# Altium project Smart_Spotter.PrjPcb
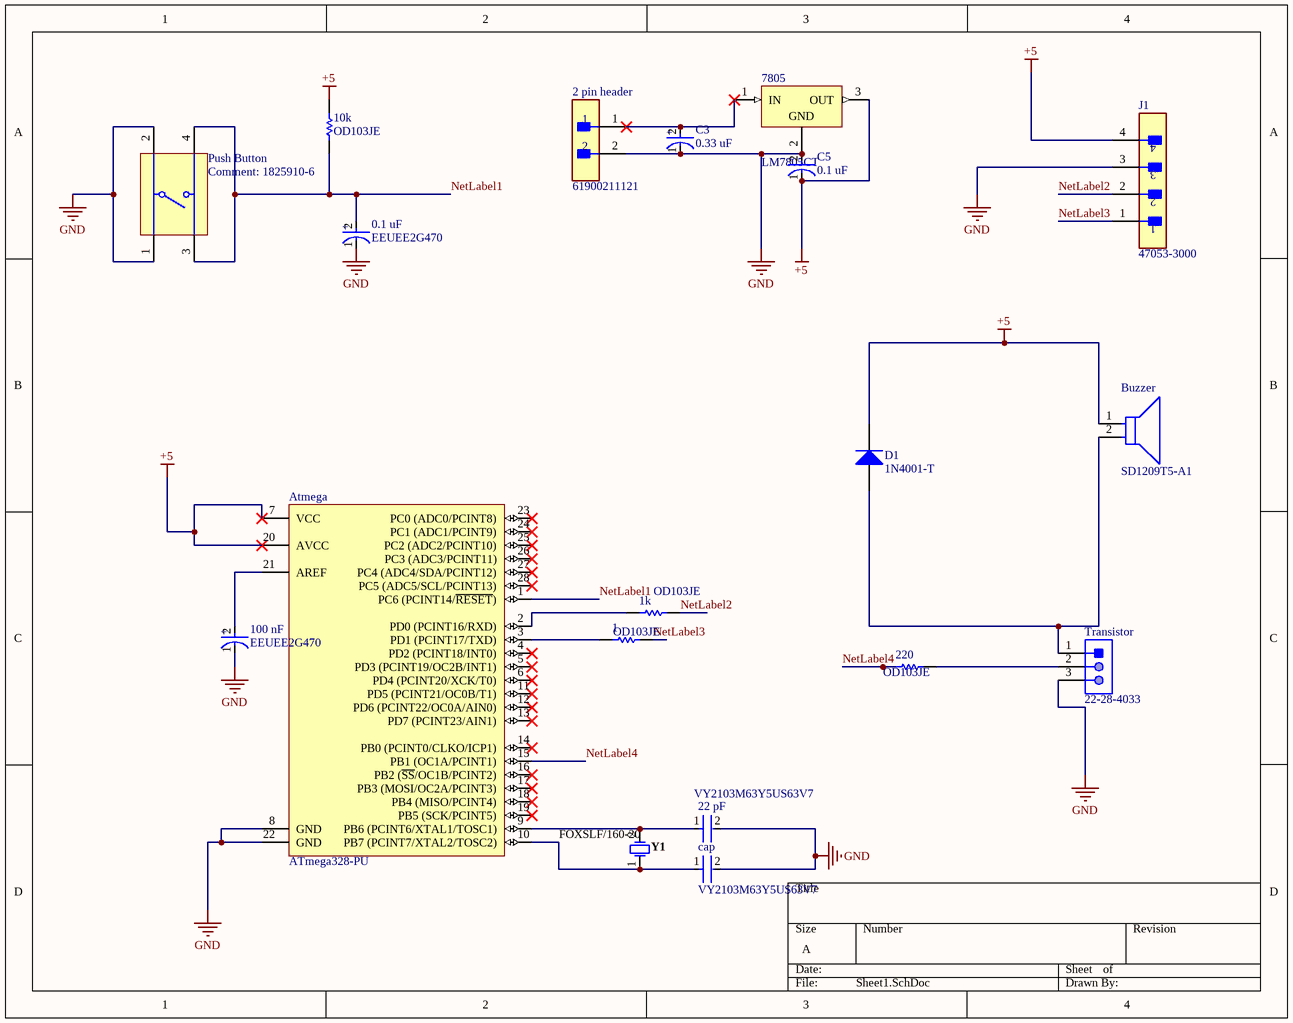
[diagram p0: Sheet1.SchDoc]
1 sheet, 19 parts. Net scope: global (net labels, ports and power ports of the same name join across sheets).
Board file: PCB2.PcbDoc

## Sheet Sheet1.SchDoc
size A; SheetNumber: 1; SheetTotal: 1

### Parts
0.1_uF  EEUEE2G470  [FP-RAD-TH-D_16_0_5-L_25_2-MFG]
1  OD103JE  [OMTE-RES7X2.5-2]
1k  OD103JE  [OMTE-RES7X2.5-2]
2_pin_header  61900211121  [FP-61900211121-MFG]
10k  OD103JE  [OMTE-RES7X2.5-2]
22_pF  VY2103M63Y5US63V7  [FP-VY2103M63Y5US63V7-MFG]
100_nF  EEUEE2G470  [FP-RAD-TH-D_16_0_5-L_25_2-MFG]
220  OD103JE  [OMTE-RES7X2.5-2]
7805  LM7805CT  [FAIR-TO-220-3]
Atmega  ATmega328-PU  [28P3]
Buzzer  SD1209T5-A1  [FP-SD1209-MFG]
C3  0.33 uF  [FP-RAD-TH-D_16_0_5-L_25_2-MFG]
C5  0.1 uF  [FP-RAD-TH-D_16_0_5-L_25_2-MFG]
cap  VY2103M63Y5US63V7  [FP-VY2103M63Y5US63V7-MFG]
D1  1N4001-T  [DIOD-DO-41-P-2_V]
J1  47053-3000  [FP-47053-3000-MFG]
Push_Button  1825910-6  [TECO-1825910-6_V]
Transistor  22-28-4033  [MOLX-22-28-4033_V]
Y1  FOXSLF/160-20  [FOX-FOXSLF160-20]

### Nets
+5: 10k.1 7805.3(OUT) Atmega.7(VCC) Atmega.20(AVCC) Buzzer.1(C) C5.1(C) D1.2(K) J1.4
GND: 0.1_uF.1(C) 2_pin_header.2 22_pF.2 100_nF.1(C) 7805.2(GND) Atmega.8(GND) Atmega.22(GND) C3.1(C) C5.2(A) cap.2 J1.3 Push_Button.1 Push_Button.2 Transistor.3
NetLabel1: 0.1_uF.2(A) 10k.2 Atmega.1(PC6_(PCINT14/~{RESET})) Push_Button.3 Push_Button.4
NetLabel2: 1k.2 J1.2
NetLabel3: 1.2 J1.1
NetLabel4: 220.1 Atmega.15(PB1_(OC1A/PCINT1))
Net1_1: 1.1 Atmega.3(PD1_(PCINT17/TXD))
Net1k_1: 1k.1 Atmega.2(PD0_(PCINT16/RXD))
Net2_pin_header_1: 2_pin_header.1 7805.1(IN) C3.2(A)
Net22_pF_1: 22_pF.1 Atmega.9(PB6_(PCINT6/XTAL1/TOSC1)) Y1.2
Net100_nF_2: 100_nF.2(A) Atmega.21(AREF)
Net220_2: 220.2 Transistor.2
NetAtmega_10: Atmega.10(PB7_(PCINT7/XTAL2/TOSC2)) cap.1 Y1.1
NetBuzzer_2: Buzzer.2(A) D1.1(A) Transistor.1

Not connected (* = marked no-connect by the designer): Atmega 4(PD2_(PCINT18/INT0))* 5(PD3_(PCINT19/OC2B/INT1))* 6(PD4_(PCINT20/XCK/T0))* 11(PD5_(PCINT21/OC0B/T1))* 12(PD6_(PCINT22/OC0A/AIN0))* 13(PD7_(PCINT23/AIN1))* 14(PB0_(PCINT0/CLKO/ICP1))* 16(PB2_(~{SS}/OC1B/PCINT2))* 17(PB3_(MOSI/OC2A/PCINT3))* 18(PB4_(MISO/PCINT4))* 19(PB5_(SCK/PCINT5))* 23(PC0_(ADC0/PCINT8))* 24(PC1_(ADC1/PCINT9))* 25(PC2_(ADC2/PCINT10))* 26(PC3_(ADC3/PCINT11))* 27(PC4_(ADC4/SDA/PCINT12))* 28(PC5_(ADC5/SCL/PCINT13))*

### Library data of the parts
0.1_uF 100_nF C3 C5 = CMP-05427-001116-1: Aluminum Electrolytic Capacitors (Radial Lead Type) 47uF ±20% 400V; Ripple Current (AC): 1.18A; Dissipation Factor: 0.24%; Dielectric Material: Aluminium; Life (Hours): 10000Hour; Lead Diameter: 0.8mm; Leakage Current: 1.138mA
1 1k 10k 220 = CMP-2000-06865-1: Little Demon(R) Carbon Composition Molded OD Series, 250 V, 10 KOhm, +/-5%, -70 to 130 degC, 2-Pin THD, RoHS, Bulk; Manufacturer: Ohmite; Resistance (Ohms): 10k; Power Rating: 0.25W; Power (Watts): 0.25W,1/4W; Tolerance: ±5%; Online Catalog: OD,OF,OASeries,LittleDemon®; Catalog Drawings: OD,OF,OASeries; EDA / CAD Models: DownloadfromAcceleratedDesigns
2_pin_header = CMP-1502-00584-2: CONN HEADER VERT 2POS 2.54MM; Number of Contacts: 2; Gender: Male; Current Rating: 3A; Voltage Rating: 250V; Insulation Resistance: 1GR
22_pF cap = CMP-02417-000049-1: CAP CER 10000PF 440VAC Y5U RDL; Tolerance: 20%; Lead/Base Style: Kinked; Voltage Rating (AC): 300V; Lead Length: 30mm; Lead Diameter: 0.6mm; Capacitance: 10nF
7805 = CMP-2000-04938-1: Positive Voltage Regulator, 5 V, 1 A, -40 to 125 degC, 3-Pin TO-220, RoHS, Tube; Manufacturer: FairchildSemiconductor; Maximum Input Voltage: 35V; Maximum Quiescent Current: 8mA; Load Regulation: 100mV; Maximum Output Current: 2.2(Typ)A; Output Type: Fixed; Typical Dropout Voltage @ Current: 2@1AV; Rad Hard: No; Output Voltage: 5V; Accuracy: ±4%; Number of Outputs: 1
Atmega = CMP-0095-00015-2: 8-bit AVR Microcontroller, 32KB Flash, 1KB EEPROM, 2KB SRAM, 28-pin PDIP, Industrial Grade (-40°C to 85°C)
Buzzer = CMP-08413-000009-1: AUDIO MAGNETIC XDCR 3-6V TH; Max Supply Current: 60mA; Number of Terminals/Pins: 2; Frequency: 2.048kHz; Washable: No; Operating Supply Voltage: 5V; Self Resonant Frequency: 2.05kHz
D1 = CMP-0639-00006-2: 1.0 A Rectifier, 15 pF, 50 V, -65 to 150 degC, 2-Pin DO-41 Plastic, RoHS, Tape and Reel; Manufacturer: Diodes Inc; VF (V): 1; CT (pF): 15; Max. IR (uA): 5; VRRM (V): 50; Max. IFSM (A): 30
J1 = CMP-04776-000447-1: CONN HEADER VERT 4POS 2.54MM; Glow Wire Compliant: Non-compliant; Voltage Rating: 250V; Current Rating: 4A; Number of Circuits: 4; Gender: Male
Push_Button = CMP-1684-00021-1: Tact Switch, SPST-NO, 0.05 A, -35 to 85 degC, 4-Pin THD, RoHS, Bulk; Manufacturer: TE Connectivity; Maximum Contact Resistance: 100mOhm; Mechanical Life: 100000Cycles; Bushing Type: Unthreaded; Switch Configuration: OFF(ON); Maximum DC Voltage Rating: 24V; Contact Rating @ Voltage: 0.05A@24VDC; Actuator Color: Black; Body Orientation: Straight; Function: MomentaryContact; Illumination: N/R; Actuator Style: RoundButton; Actuator Material: PolybutyleneTerephthalate; Dielectric Strength: 500VAC; Pole Throw Configuration: SPST; Actuator Length: 1.4mm
Transistor = CMP-1676-00001-5: Male Header, Pitch 2.54 mm, 1 x 3 Position, Height 8.38 mm, Tail Length 3.18 mm, RoHS, Bulk; Manufacturer: Molex; Rows: 1; Voltage Rating: 250 V; Current Rating: 4 A
Y1 = CMP-1749-00003-1: Resistance Weld Thru-Hole Crystal, 16 MHz, -20 to 70 degC, 2-Pin THD, RoHS, Bulk; Voltage Rating: 250 V; Tolerance: 1%; Resistance: 221 kohm; Case\Package: Axial; Power Rating: 250 mW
